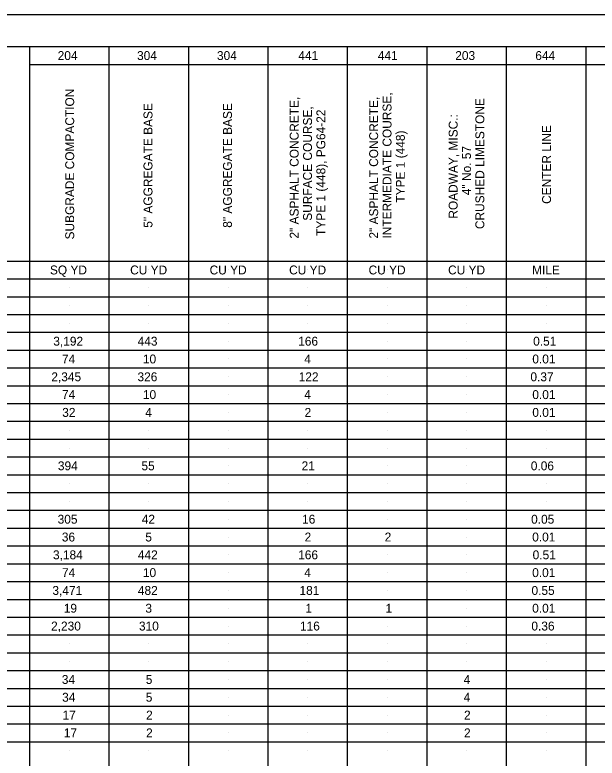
# Model space of a CAD drawing. Extents: x 2107022.8 to 2107056.8, y 706071 to 706093.
# Drawn here: x 2107038.83 to 2107047.99, y 706081.3 to 706092.99 of the extents above; entities that cross this region are included whole.
import ezdxf

# ---------------------------------------------------------------- set-up
doc = ezdxf.new("R2010")
doc.units = 0
for name, color, linetype in [('SC_Scratch1', 7, 'Continuous'), ('SH_Border', 7, 'Continuous'), ('SH_Cut_Line', 7, 'Continuous'), ('SH_Data', 7, 'Continuous'), ('SH_Text', 7, 'Continuous')]:
    doc.layers.add(name, color=color, linetype=linetype)

msp = doc.modelspace()

# ---------------------------------------------------------------- linework, layer by layer
at = {"layer": 'SC_Scratch1'}
for p, q in [((2107039.687, 706092.347), (2107039.687, 706092.347)), ((2107040.937, 706092.347), (2107040.937, 706092.347)), ((2107042.187, 706092.347), (2107042.187, 706092.347)), ((2107043.437, 706092.347), (2107043.437, 706092.347)), ((2107044.687, 706092.347), (2107044.687, 706092.347)), ((2107045.937, 706092.347), (2107045.937, 706092.347)), ((2107047.187, 706092.347), (2107047.187, 706092.347)), ((2107039.687, 706088.975), (2107039.687, 706088.975)), ((2107040.937, 706088.975), (2107040.937, 706088.975)), ((2107042.187, 706088.975), (2107042.187, 706088.975)), ((2107043.437, 706088.975), (2107043.437, 706088.975)), ((2107044.687, 706088.975), (2107044.687, 706088.975)), ((2107045.937, 706088.975), (2107045.937, 706088.975)), ((2107047.187, 706088.975), (2107047.187, 706088.975)), ((2107039.687, 706088.695), (2107039.687, 706088.695)), ((2107040.937, 706088.695), (2107040.937, 706088.695)), ((2107042.187, 706088.695), (2107042.187, 706088.695)), ((2107043.437, 706088.695), (2107043.437, 706088.695)), ((2107044.687, 706088.695), (2107044.687, 706088.695)), ((2107045.937, 706088.695), (2107045.937, 706088.695)), ((2107047.187, 706088.695), (2107047.187, 706088.695)), ((2107039.687, 706088.415), (2107039.687, 706088.415)), ((2107040.937, 706088.415), (2107040.937, 706088.415)), ((2107042.187, 706088.415), (2107042.187, 706088.415)), ((2107043.437, 706088.415), (2107043.437, 706088.415)), ((2107044.687, 706088.415), (2107044.687, 706088.415)), ((2107045.937, 706088.415), (2107045.937, 706088.415)), ((2107047.187, 706088.415), (2107047.187, 706088.415)), ((2107039.687, 706088.135), (2107039.687, 706088.135)), ((2107040.937, 706088.135), (2107040.937, 706088.135)), ((2107042.187, 706088.135), (2107042.187, 706088.135)), ((2107043.437, 706088.135), (2107043.437, 706088.135)), ((2107044.687, 706088.135), (2107044.687, 706088.135)), ((2107045.937, 706088.135), (2107045.937, 706088.135)), ((2107047.187, 706088.135), (2107047.187, 706088.135)), ((2107039.687, 706087.855), (2107039.687, 706087.855)), ((2107040.937, 706087.855), (2107040.937, 706087.855)), ((2107042.187, 706087.855), (2107042.187, 706087.855)), ((2107043.437, 706087.855), (2107043.437, 706087.855)), ((2107044.687, 706087.855), (2107044.687, 706087.855)), ((2107045.937, 706087.855), (2107045.937, 706087.855)), ((2107047.187, 706087.855), (2107047.187, 706087.855)), ((2107039.687, 706087.575), (2107039.687, 706087.575)), ((2107040.937, 706087.575), (2107040.937, 706087.575)), ((2107042.187, 706087.575), (2107042.187, 706087.575)), ((2107043.437, 706087.575), (2107043.437, 706087.575)), ((2107044.687, 706087.575), (2107044.687, 706087.575)), ((2107045.937, 706087.575), (2107045.937, 706087.575)), ((2107047.187, 706087.575), (2107047.187, 706087.575)), ((2107039.687, 706087.295), (2107039.687, 706087.295)), ((2107040.937, 706087.295), (2107040.937, 706087.295)), ((2107042.187, 706087.295), (2107042.187, 706087.295)), ((2107043.437, 706087.295), (2107043.437, 706087.295)), ((2107044.687, 706087.295), (2107044.687, 706087.295)), ((2107045.937, 706087.295), (2107045.937, 706087.295)), ((2107047.187, 706087.295), (2107047.187, 706087.295)), ((2107039.687, 706087.015), (2107039.687, 706087.015)), ((2107040.937, 706087.015), (2107040.937, 706087.015)), ((2107042.187, 706087.015), (2107042.187, 706087.015)), ((2107043.437, 706087.015), (2107043.437, 706087.015)), ((2107044.687, 706087.015), (2107044.687, 706087.015)), ((2107045.937, 706087.015), (2107045.937, 706087.015)), ((2107047.187, 706087.015), (2107047.187, 706087.015)), ((2107039.687, 706086.735), (2107039.687, 706086.735)), ((2107040.937, 706086.735), (2107040.937, 706086.735)), ((2107042.187, 706086.735), (2107042.187, 706086.735)), ((2107043.437, 706086.735), (2107043.437, 706086.735)), ((2107044.687, 706086.735), (2107044.687, 706086.735)), ((2107045.937, 706086.735), (2107045.937, 706086.735)), ((2107047.187, 706086.735), (2107047.187, 706086.735)), ((2107039.687, 706086.455), (2107039.687, 706086.455)), ((2107040.937, 706086.455), (2107040.937, 706086.455)), ((2107042.187, 706086.455), (2107042.187, 706086.455)), ((2107043.437, 706086.455), (2107043.437, 706086.455)), ((2107044.687, 706086.455), (2107044.687, 706086.455)), ((2107045.937, 706086.455), (2107045.937, 706086.455)), ((2107047.187, 706086.455), (2107047.187, 706086.455)), ((2107039.687, 706086.175), (2107039.687, 706086.175)), ((2107040.937, 706086.175), (2107040.937, 706086.175)), ((2107042.187, 706086.175), (2107042.187, 706086.175)), ((2107043.437, 706086.175), (2107043.437, 706086.175)), ((2107044.687, 706086.175), (2107044.687, 706086.175)), ((2107045.937, 706086.175), (2107045.937, 706086.175)), ((2107047.187, 706086.175), (2107047.187, 706086.175)), ((2107039.687, 706085.895), (2107039.687, 706085.895)), ((2107040.937, 706085.895), (2107040.937, 706085.895)), ((2107042.187, 706085.895), (2107042.187, 706085.895)), ((2107043.437, 706085.895), (2107043.437, 706085.895)), ((2107044.687, 706085.895), (2107044.687, 706085.895)), ((2107045.937, 706085.895), (2107045.937, 706085.895)), ((2107047.187, 706085.895), (2107047.187, 706085.895)), ((2107039.687, 706085.615), (2107039.687, 706085.615)), ((2107040.937, 706085.615), (2107040.937, 706085.615)), ((2107042.187, 706085.615), (2107042.187, 706085.615)), ((2107043.437, 706085.615), (2107043.437, 706085.615)), ((2107044.687, 706085.615), (2107044.687, 706085.615)), ((2107045.937, 706085.615), (2107045.937, 706085.615)), ((2107047.187, 706085.615), (2107047.187, 706085.615)), ((2107039.687, 706085.335), (2107039.687, 706085.335)), ((2107040.937, 706085.335), (2107040.937, 706085.335)), ((2107042.187, 706085.335), (2107042.187, 706085.335)), ((2107043.437, 706085.335), (2107043.437, 706085.335)), ((2107044.687, 706085.335), (2107044.687, 706085.335)), ((2107045.937, 706085.335), (2107045.937, 706085.335)), ((2107047.187, 706085.335), (2107047.187, 706085.335)), ((2107039.687, 706085.055), (2107039.687, 706085.055)), ((2107040.937, 706085.055), (2107040.937, 706085.055)), ((2107042.187, 706085.055), (2107042.187, 706085.055)), ((2107043.437, 706085.055), (2107043.437, 706085.055)), ((2107044.687, 706085.055), (2107044.687, 706085.055)), ((2107045.937, 706085.055), (2107045.937, 706085.055)), ((2107047.187, 706085.055), (2107047.187, 706085.055)), ((2107039.687, 706084.775), (2107039.687, 706084.775)), ((2107040.937, 706084.775), (2107040.937, 706084.775)), ((2107042.187, 706084.775), (2107042.187, 706084.775)), ((2107043.437, 706084.775), (2107043.437, 706084.775)), ((2107044.687, 706084.775), (2107044.687, 706084.775)), ((2107045.937, 706084.775), (2107045.937, 706084.775)), ((2107047.187, 706084.775), (2107047.187, 706084.775)), ((2107039.687, 706084.495), (2107039.687, 706084.495)), ((2107040.937, 706084.495), (2107040.937, 706084.495)), ((2107042.187, 706084.495), (2107042.187, 706084.495)), ((2107043.437, 706084.495), (2107043.437, 706084.495)), ((2107044.687, 706084.495), (2107044.687, 706084.495)), ((2107045.937, 706084.495), (2107045.937, 706084.495)), ((2107047.187, 706084.495), (2107047.187, 706084.495)), ((2107039.687, 706084.215), (2107039.687, 706084.215)), ((2107040.937, 706084.215), (2107040.937, 706084.215)), ((2107042.187, 706084.215), (2107042.187, 706084.215)), ((2107043.437, 706084.215), (2107043.437, 706084.215)), ((2107044.687, 706084.215), (2107044.687, 706084.215)), ((2107045.937, 706084.215), (2107045.937, 706084.215)), ((2107047.187, 706084.215), (2107047.187, 706084.215)), ((2107039.687, 706083.935), (2107039.687, 706083.935)), ((2107040.937, 706083.935), (2107040.937, 706083.935)), ((2107042.187, 706083.935), (2107042.187, 706083.935)), ((2107043.437, 706083.935), (2107043.437, 706083.935)), ((2107044.687, 706083.935), (2107044.687, 706083.935)), ((2107045.937, 706083.935), (2107045.937, 706083.935)), ((2107047.187, 706083.935), (2107047.187, 706083.935)), ((2107039.687, 706083.655), (2107039.687, 706083.655)), ((2107040.937, 706083.655), (2107040.937, 706083.655)), ((2107042.187, 706083.655), (2107042.187, 706083.655)), ((2107043.437, 706083.655), (2107043.437, 706083.655)), ((2107044.687, 706083.655), (2107044.687, 706083.655)), ((2107045.937, 706083.655), (2107045.937, 706083.655)), ((2107047.187, 706083.655), (2107047.187, 706083.655)), ((2107039.687, 706083.375), (2107039.687, 706083.375)), ((2107040.937, 706083.375), (2107040.937, 706083.375)), ((2107042.187, 706083.375), (2107042.187, 706083.375)), ((2107043.437, 706083.375), (2107043.437, 706083.375)), ((2107044.687, 706083.375), (2107044.687, 706083.375)), ((2107045.937, 706083.375), (2107045.937, 706083.375)), ((2107047.187, 706083.375), (2107047.187, 706083.375)), ((2107039.687, 706083.095), (2107039.687, 706083.095)), ((2107040.937, 706083.095), (2107040.937, 706083.095)), ((2107042.187, 706083.095), (2107042.187, 706083.095)), ((2107043.437, 706083.095), (2107043.437, 706083.095)), ((2107044.687, 706083.095), (2107044.687, 706083.095)), ((2107045.937, 706083.095), (2107045.937, 706083.095)), ((2107047.187, 706083.095), (2107047.187, 706083.095)), ((2107039.687, 706082.815), (2107039.687, 706082.815)), ((2107040.937, 706082.815), (2107040.937, 706082.815)), ((2107042.187, 706082.815), (2107042.187, 706082.815)), ((2107043.437, 706082.815), (2107043.437, 706082.815)), ((2107044.687, 706082.815), (2107044.687, 706082.815)), ((2107045.937, 706082.815), (2107045.937, 706082.815)), ((2107047.187, 706082.815), (2107047.187, 706082.815)), ((2107039.687, 706082.535), (2107039.687, 706082.535)), ((2107040.937, 706082.535), (2107040.937, 706082.535)), ((2107042.187, 706082.535), (2107042.187, 706082.535)), ((2107043.437, 706082.535), (2107043.437, 706082.535)), ((2107044.687, 706082.535), (2107044.687, 706082.535)), ((2107045.937, 706082.535), (2107045.937, 706082.535)), ((2107047.187, 706082.535), (2107047.187, 706082.535)), ((2107039.687, 706082.255), (2107039.687, 706082.255)), ((2107040.937, 706082.255), (2107040.937, 706082.255)), ((2107042.187, 706082.255), (2107042.187, 706082.255)), ((2107043.437, 706082.255), (2107043.437, 706082.255)), ((2107044.687, 706082.255), (2107044.687, 706082.255)), ((2107045.937, 706082.255), (2107045.937, 706082.255)), ((2107047.187, 706082.255), (2107047.187, 706082.255)), ((2107039.687, 706081.975), (2107039.687, 706081.975)), ((2107040.937, 706081.975), (2107040.937, 706081.975)), ((2107042.187, 706081.975), (2107042.187, 706081.975)), ((2107043.437, 706081.975), (2107043.437, 706081.975)), ((2107044.687, 706081.975), (2107044.687, 706081.975)), ((2107045.937, 706081.975), (2107045.937, 706081.975)), ((2107047.187, 706081.975), (2107047.187, 706081.975)), ((2107039.687, 706081.695), (2107039.687, 706081.695)), ((2107040.937, 706081.695), (2107040.937, 706081.695)), ((2107042.187, 706081.695), (2107042.187, 706081.695)), ((2107043.437, 706081.695), (2107043.437, 706081.695)), ((2107044.687, 706081.695), (2107044.687, 706081.695)), ((2107045.937, 706081.695), (2107045.937, 706081.695)), ((2107047.187, 706081.695), (2107047.187, 706081.695)), ((2107039.687, 706081.415), (2107039.687, 706081.415)), ((2107040.937, 706081.415), (2107040.937, 706081.415)), ((2107042.187, 706081.415), (2107042.187, 706081.415)), ((2107043.437, 706081.415), (2107043.437, 706081.415)), ((2107044.687, 706081.415), (2107044.687, 706081.415)), ((2107045.937, 706081.415), (2107045.937, 706081.415)), ((2107047.187, 706081.415), (2107047.187, 706081.415))]:
    msp.add_line(p, q, dxfattribs=at)
at = {"layer": 'SH_Border'}
msp.add_lwpolyline([(2107024.812, 706092.487), (2107056.312, 706092.487), (2107056.312, 706071.487), (2107024.812, 706071.487)], close=True, dxfattribs=at)
at = {"layer": 'SH_Cut_Line'}
msp.add_lwpolyline([(2107022.812, 706070.987), (2107056.812, 706070.987), (2107056.812, 706092.987), (2107022.812, 706092.987)], close=True, dxfattribs=at)
at = {"layer": 'SH_Data'}
for p, q in [((2107039.062, 706071.487), (2107039.062, 706092.487)), ((2107040.312, 706071.487), (2107040.312, 706092.487)), ((2107041.562, 706072.035), (2107041.562, 706092.487)), ((2107042.812, 706071.487), (2107042.812, 706092.487)), ((2107044.062, 706071.487), (2107044.062, 706092.487)), ((2107045.312, 706071.487), (2107045.312, 706092.487)), ((2107046.562, 706071.487), (2107046.562, 706092.487)), ((2107047.812, 706071.487), (2107047.812, 706092.487)), ((2107039.062, 706092.207), (2107055.312, 706092.207)), ((2107033.062, 706089.115), (2107055.312, 706089.115)), ((2107024.812, 706088.835), (2107055.312, 706088.835)), ((2107024.812, 706088.555), (2107055.312, 706088.555)), ((2107024.812, 706088.275), (2107055.312, 706088.275)), ((2107024.812, 706087.995), (2107055.312, 706087.995)), ((2107024.812, 706087.715), (2107055.312, 706087.715)), ((2107024.812, 706087.435), (2107055.312, 706087.435)), ((2107024.812, 706087.155), (2107055.312, 706087.155)), ((2107024.812, 706086.875), (2107055.312, 706086.875)), ((2107024.812, 706086.595), (2107055.312, 706086.595)), ((2107024.812, 706086.315), (2107055.312, 706086.315)), ((2107024.812, 706086.035), (2107055.312, 706086.035)), ((2107024.812, 706085.755), (2107055.312, 706085.755)), ((2107024.812, 706085.475), (2107055.312, 706085.475)), ((2107024.812, 706085.195), (2107055.312, 706085.195)), ((2107024.812, 706084.915), (2107055.312, 706084.915)), ((2107024.812, 706084.635), (2107055.312, 706084.635)), ((2107024.812, 706084.355), (2107055.312, 706084.355)), ((2107024.812, 706084.075), (2107055.312, 706084.075)), ((2107024.812, 706083.795), (2107055.312, 706083.795)), ((2107024.812, 706083.515), (2107055.312, 706083.515)), ((2107024.812, 706083.235), (2107055.312, 706083.235)), ((2107024.812, 706082.955), (2107055.312, 706082.955)), ((2107024.812, 706082.675), (2107055.312, 706082.675)), ((2107024.812, 706082.395), (2107055.312, 706082.395)), ((2107024.812, 706082.115), (2107055.312, 706082.115)), ((2107024.812, 706081.835), (2107055.312, 706081.835)), ((2107024.812, 706081.555), (2107055.312, 706081.555))]:
    msp.add_line(p, q, dxfattribs=at)

# ---------------------------------------------------------------- texts
at = {"layer": 'SH_Text'}
for s, p in [('204', (2107039.502, 706092.277)), ('304', (2107040.75, 706092.277)), ('304', (2107042.007, 706092.277)), ('441', (2107043.286, 706092.277)), ('441', (2107044.536, 706092.277)), ('203', (2107045.754, 706092.277)), ('644', (2107047.013, 706092.277)), ('SQ YD', (2107039.38, 706088.905)), ('CU YD', (2107040.641, 706088.905)), ('CU YD', (2107041.891, 706088.905)), ('CU YD', (2107043.141, 706088.905)), ('CU YD', (2107044.391, 706088.905)), ('CU YD', (2107045.641, 706088.905)), ('MILE', (2107046.962, 706088.905)), ('3,192', (2107039.433, 706087.785)), ('443', (2107040.759, 706087.785)), ('166', (2107043.284, 706087.785)), ('0.51', (2107046.979, 706087.785)), ('74', (2107039.569, 706087.505)), ('10', (2107040.842, 706087.505)), ('4', (2107043.379, 706087.505)), ('0.01', (2107046.966, 706087.505)), ('2,345', (2107039.402, 706087.225)), ('326', (2107040.757, 706087.225)), ('122', (2107043.292, 706087.225)), ('0.37', (2107046.936, 706087.225)), ('74', (2107039.569, 706086.945)), ('10', (2107040.842, 706086.945)), ('4', (2107043.379, 706086.945)), ('0.01', (2107046.966, 706086.945)), ('32', (2107039.573, 706086.665)), ('4', (2107040.879, 706086.665)), ('2', (2107043.385, 706086.665)), ('0.01', (2107046.966, 706086.665)), ('394', (2107039.505, 706085.825)), ('55', (2107040.819, 706085.825)), ('21', (2107043.338, 706085.825)), ('0.06', (2107046.942, 706085.825)), ('305', (2107039.501, 706084.985)), ('42', (2107040.824, 706084.985)), ('16', (2107043.345, 706084.985)), ('0.05', (2107046.947, 706084.985)), ('36', (2107039.567, 706084.705)), ('5', (2107040.88, 706084.705)), ('2', (2107043.385, 706084.705)), ('2', (2107044.644, 706084.705)), ('0.01', (2107046.964, 706084.705)), ('3,184', (2107039.428, 706084.425)), ('442', (2107040.763, 706084.425)), ('166', (2107043.284, 706084.425)), ('0.51', (2107046.971, 706084.425)), ('74', (2107039.569, 706084.145)), ('10', (2107040.842, 706084.145)), ('4', (2107043.379, 706084.145)), ('0.01', (2107046.964, 706084.145)), ('3,471', (2107039.419, 706083.865)), ('482', (2107040.763, 706083.865)), ('181', (2107043.304, 706083.865)), ('0.55', (2107046.953, 706083.865)), ('19', (2107039.598, 706083.585)), ('3', (2107040.881, 706083.585)), ('1', (2107043.398, 706083.585)), ('1', (2107044.657, 706083.585)), ('0.01', (2107046.964, 706083.585)), ('2,230', (2107039.398, 706083.305)), ('310', (2107040.78, 706083.305)), ('116', (2107043.312, 706083.305)), ('0.36', (2107046.951, 706083.305)), ('34', (2107039.567, 706082.465)), ('5', (2107040.887, 706082.465)), ('4', (2107045.886, 706082.465)), ('34', (2107039.572, 706082.185)), ('5', (2107040.887, 706082.185)), ('4', (2107045.886, 706082.185)), ('17', (2107039.579, 706081.905)), ('2', (2107040.892, 706081.905)), ('2', (2107045.892, 706081.905)), ('17', (2107039.598, 706081.625)), ('2', (2107040.892, 706081.625)), ('2', (2107045.892, 706081.625))]:
    msp.add_text(s, height=0.14, dxfattribs=at).set_placement(p)
for s, p in [('SUBGRADE COMPACTION', (2107039.761, 706089.455)), ('INTERMEDIATE COURSE,', (2107044.751, 706089.469)), ('2" ASPHALT CONCRETE,', (2107043.291, 706089.469)), ('2" ASPHALT CONCRETE,', (2107044.541, 706089.469)), ('CRUSHED LIMESTONE', (2107046.211, 706089.618)), ('5" AGGREGATE BASE', (2107040.992, 706089.639)), ('8" AGGREGATE BASE', (2107042.242, 706089.639)), ('SURFACE COURSE,', (2107043.501, 706089.749)), ('TYPE 1 (448), PG64-22', (2107043.711, 706089.51)), ('ROADWAY, MISC.:', (2107045.791, 706089.782)), ('TYPE 1 (448)', (2107044.961, 706090.034)), ('CENTER LINE', (2107047.26, 706090.014)), ('4" No. 57', (2107046.001, 706090.151))]:
    msp.add_text(s, height=0.14, rotation=90, dxfattribs=at).set_placement(p)

doc.saveas('drawing.dxf')
